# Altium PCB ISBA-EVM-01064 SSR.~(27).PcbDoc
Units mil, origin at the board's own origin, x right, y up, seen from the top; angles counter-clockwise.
Board outline 2700 x 2000 mil, 2 copper layers (Top Layer, Bottom Layer), stack 62 mil thick; 83 components, 26 nets, 153 pads, 165 vias.
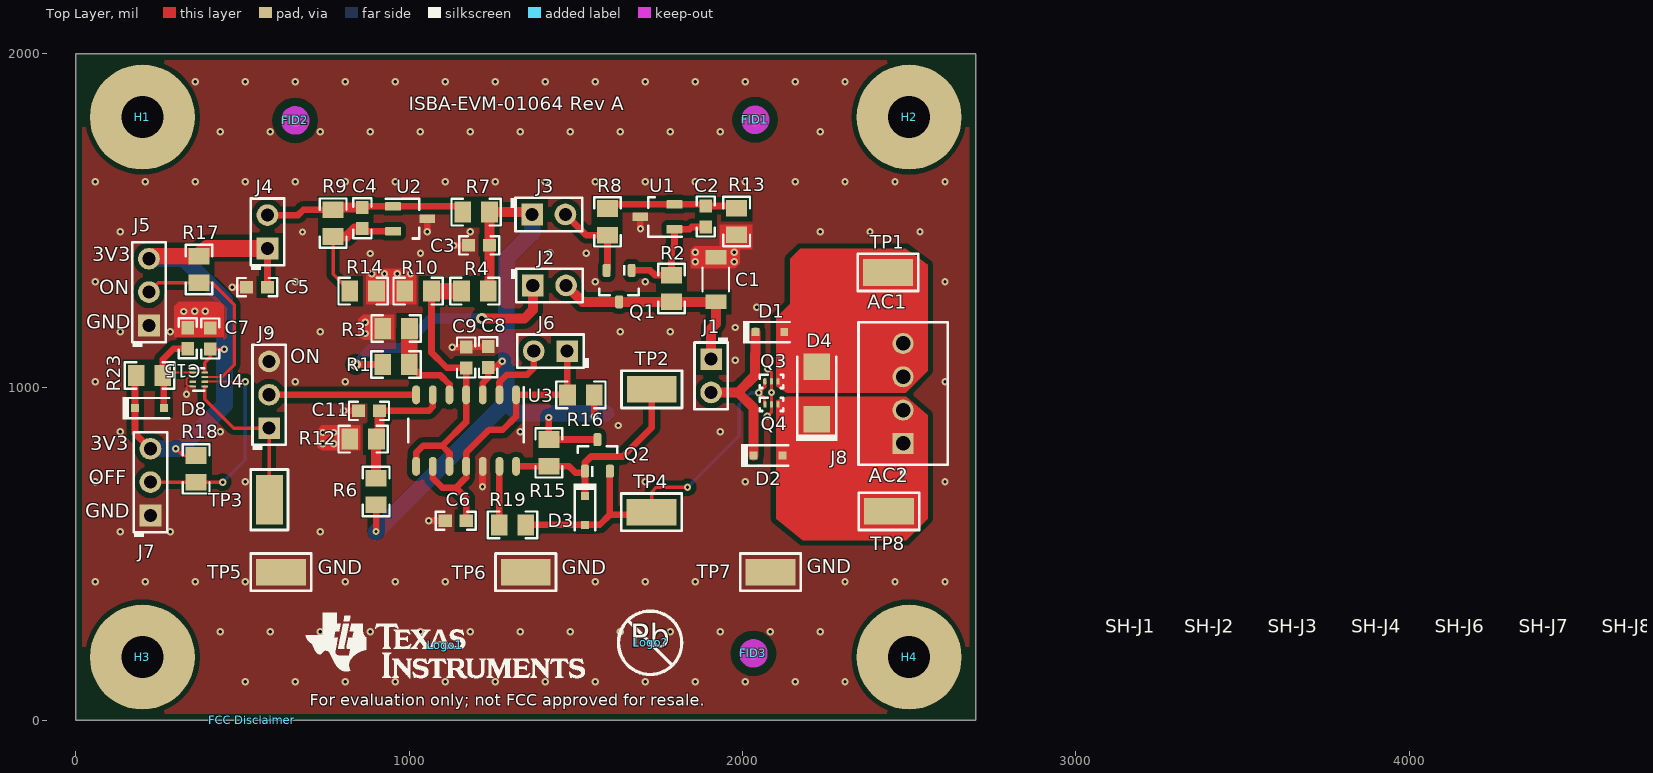
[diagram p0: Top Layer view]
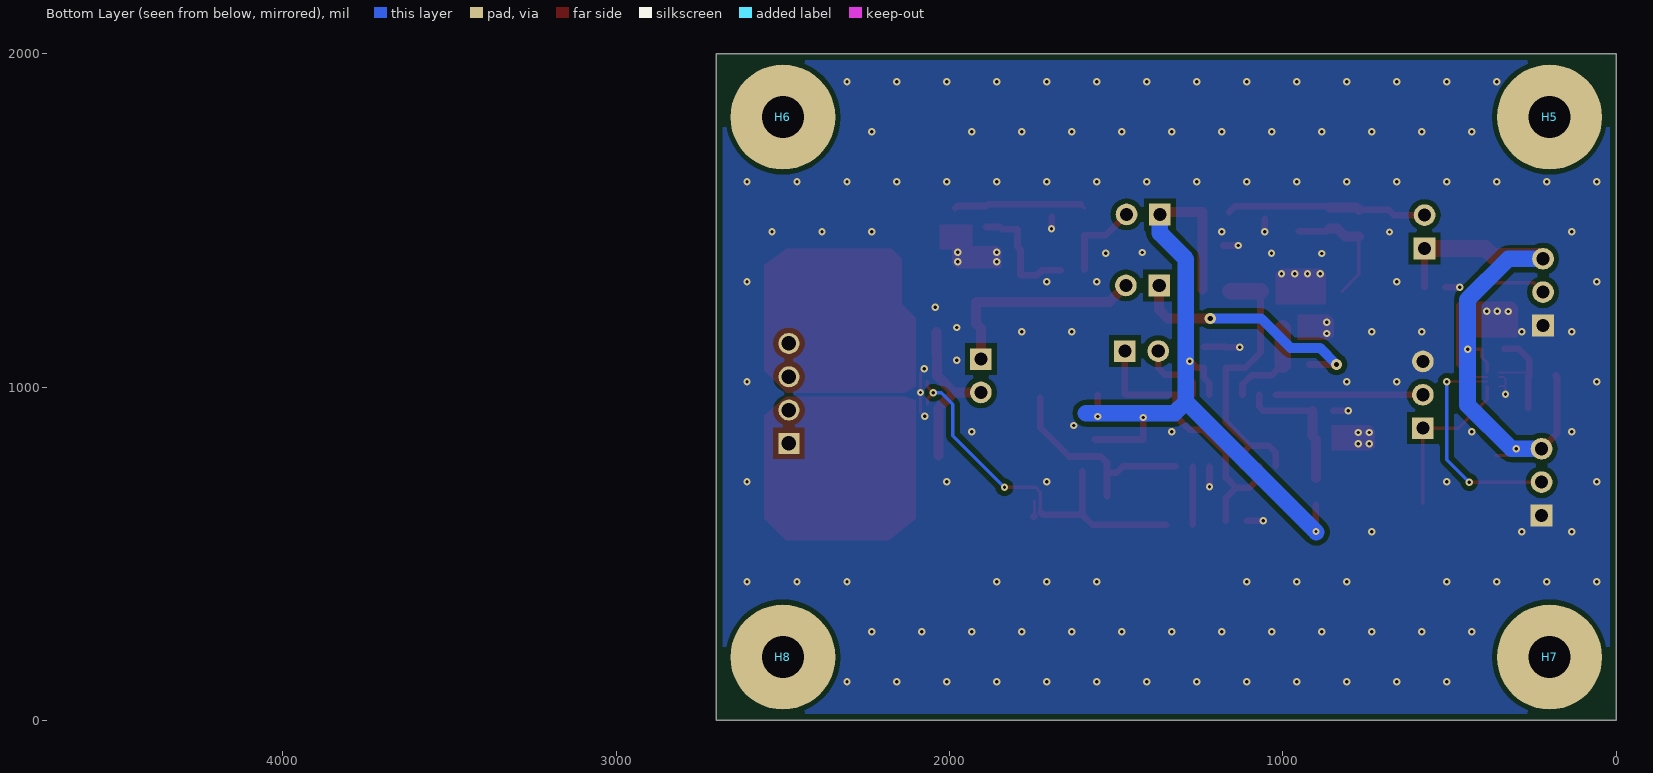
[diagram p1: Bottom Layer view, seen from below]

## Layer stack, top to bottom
Top Solder: solder mask 0.4, Solder Resist, Dk 3.5
Top Layer: signal copper 1.4
Dielectric1: core 59.2, FR-4, Dk 4.8
Bottom Layer: signal copper 1.4
Bottom Solder: solder mask 0.4, Solder Resist, Dk 3.5

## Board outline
0,0 2700,0 2700,2000 0,2000

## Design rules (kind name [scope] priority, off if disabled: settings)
AcuteAngle [All] p1: minimum=4.50000000000000E+0001 checktracksonly=FALSE
AssemblyTestPointUsage [All] p1: valid=2
Clearance Clearance_BoardEdge_MountingHoles [OnCopper and InComponentClass('Mounting Holes') vs IsKeepOut] p1: gap=25
Clearance Clearance_BoardEdge_Poly [OnCopper and InPoly vs IsKeepOut] p2: gap=25
Clearance Clearance_BoardEdge [OnCopper and Not InComponentClass('Logo') and not InComponentClass('FiducialMark') and not InRegion(1000,500,4000,800) and Not IsKeepout vs IsKeepOut] p3: gap=25
Clearance Clearance_Poly [InPolygon] p4: gap=15
Clearance [All] p5: gap=7
ComponentClearance ComponentClearance_Shunt [InComponentClass('Header') vs InComponentClass('Shunt')] p1: gap=0 collisioncheckmode=3 verticalgap=0 showdistances=FALSE
ComponentClearance ComponentClearance_Logo [InComponentClass('Logo')] p2: gap=50 collisioncheckmode=3 verticalgap=10 showdistances=FALSE
ComponentClearance ComponentClearance_ScrewToNut [(HasFootprint('NY PMS 440 0025 PH')) vs (HasFootprint('Keystone_1902C'))] p3: gap=5 collisioncheckmode=3 verticalgap=10 showdistances=FALSE
ComponentClearance ComponentClearance_MountingHoles [InComponentClass('Mounting Holes')] p4: gap=250 collisioncheckmode=3 verticalgap=100000 showdistances=FALSE
ComponentClearance ComponentClearance_SmallPassives [HasFootprint('0201*') or HasFootprint('0402*') or HasFootprint('0508') or HasFootprint('0603*') or HasFootprint('0612') or HasFootprint('0805*') or HasFootprint('0815*') or HasFootprint('0830*') or HasFootprint('1206*') or HasFootprint('1210*') or HasFootprint('1808*') or HasFootprint('1812*') or HasFootprint('1825*') or HasFootprint('2010*') or HasFootprint('2220*') or HasFootprint('2225*') or HasFootprint('2512*') or HasFootprint('2728*') or HasFootprint('3518*') vs HasFootprint('0201*') or HasFootprint('0402*') or HasFootprint('0508') or HasFootprint('0603*') or HasFootprint('0612') or HasFootprint('0805*') or HasFootprint('0815*') or HasFootprint('0830*') or HasFootprint('1206*') or HasFootprint('1210*') or HasFootprint('1808*') or HasFootprint('1812*') or HasFootprint('1825*') or HasFootprint('2010*') or HasFootprint('2220*') or HasFootprint('2225*') or HasFootprint('2512*') or HasFootprint('2728*') or HasFootprint('3518*')] p5: gap=15 collisioncheckmode=3 verticalgap=10 showdistances=FALSE
ComponentClearance ComponentClearance_THtoSMT [IsThruComponent vs IsSMTComponent] p6: gap=50 collisioncheckmode=3 verticalgap=30 showdistances=FALSE
ComponentClearance ComponentClearance_THtoTH [IsThruComponent vs IsThruComponent] p7: gap=50 collisioncheckmode=3 verticalgap=30 showdistances=FALSE
ComponentClearance [All] p8: gap=40 collisioncheckmode=3 verticalgap=10 showdistances=FALSE
DiffPairsRouting [All] p1: maxlimit=100 minlimit=10 mostfreqgap=10 toplayer_minwidth=15 toplayer_maxwidth=15 toplayer_prefwidth=15 bottomlayer_minwidth=15 bottomlayer_maxwidth=15 bottomlayer_prefwidth=15 maxuncoupledlength=1000
FabricationTestPointUsage TestPointUsage [All] p1: valid=2 allowmultiple=FALSE
FabricationTestpoint Testpoint [All] p1: side=3 testpointundercomponent=TRUE minsize=40 maxsize=100 preferedsize=60 minholesize=0 maxholesize=40 preferedholesize=32 testpointgrid=1 allowsidetop=TRUE allowsidebottom=TRUE usegrid=TRUE gridtolerance=0.01
FanoutControl Fanout_LCC [IsLCC] p1: bgadir=Out bgaviamode=Centered fanoutstyle=Auto fanoutdirection=Alternating viagrid=1 // Fanout_LCC (Default Rule)
FanoutControl Fanout_BGA [IsBGA] p2: bgadir=Out bgaviamode=Centered fanoutstyle=Auto fanoutdirection=Alternating viagrid=1 // Fanout_BGA (Default Rule)
FanoutControl Fanout_Default [All] p4: bgadir=Out bgaviamode=Centered fanoutstyle=Auto fanoutdirection=Alternating viagrid=1 // Fanout_Default (Default Rule)
FanoutControl Fanout_Small [(CompPinCount < 5)] p5: bgadir=Out bgaviamode=Centered fanoutstyle=Auto fanoutdirection=OutThenIn viagrid=1 // Fanout_Small (Default Rule)
HoleSize [All] p1: absolutevalues=TRUE maxlimit=251 minlimit=8 maxpercent=80.000 minpercent=20.000
MinimumAnnularRing MinimumAnnularRing_ThermalPadVias [IsVia and InAnyComponent] p1: minimumring=5.91
MinimumAnnularRing [All] p2: minimumring=5
MinimumSolderMaskSliver MinimumSolderMaskSliver_Logo [InComponentClass('Logo') vs InComponentClass('Logo')] p1: minsoldermaskwidth=0.7
MinimumSolderMaskSliver [All] p2: minsoldermaskwidth=3.94
PlaneClearance [All] p1: clearance=15
PlaneConnect [All] p1: planeconnectstyle=Direct reliefexpansion=10 reliefentries=4 reliefconductorwidth=10 reliefairgap=10
PolygonConnect [All] p1: connectstyle=Direct reliefconductorwidth=10 reliefentries=4 polygonreliefangle="90 Angle" airgapwidth=10
RoutingVias ThermalPadVias [IsVia and InAnyComponent] p1: holewidth=7.87 width=19.68 viastyle="Through Hole" minholewidth=7.87 minwidth=19.68 maxholewidth=12.99 maxwidth=23.62
RoutingVias [All] p2: holewidth=16 width=34 viastyle="Through Hole" minholewidth=7.87 minwidth=19 maxholewidth=40 maxwidth=65
SMDToCorner [All] p1: distance=30000
SilkToBoardRegionClearance [Not ((IsComment or IsDesignator) And (Hide <> 'False')) and not InRegion(1000,500,4000,800)] p1:
SilkToSilkClearance [All] p1: silktosilkclearance=0
SilkToSolderMaskClearance SilkscreenOverComponentPads [IsPad] p1: minsilkscreentomaskgap=0 clearancetoexposedcopper=TRUE
SolderMaskExpansion [All] p1: expansion=1.97
Width [All] p1: maxlimit=100 minlimit=6 preferedwidth=10 checkconnectedcopper=TRUE
14 further rules are at their usual default settings.

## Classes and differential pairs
component class Shunt: SH-J1 SH-J2 SH-J3 SH-J4 SH-J6 SH-J7 SH-J8
component class "ISBA-EVM-01064 SSR_Relay": C1 C2 C3 C4 C5 C6 C7 C8 C9 C11 C15 D1 D2 D3 D4 D8 J1 J2 J3 J4 J5 J6 J7 J8 J9 Q1 Q2 Q3 Q4 R1 R2 R3 R4 R6 R7 R8 R9 R10 R12 R13 R14 R15 R16 R17 R18 R19 R23 TP1 TP2 TP3 TP4 TP5 TP6 TP7 TP8 U1 U2 U3 U4
component class Header: J1 J2 J3 J4 J5 J6 J7 J9
component class "Mounting Holes": H1 H2 H3 H4
component class Logo: Logo1
component class "ISBA-EVM-01064 SSR_TID_Hardware": "FCC Disclaimer" FID1 FID2 FID3 H1 H2 H3 H4 H5 H6 H7 H8 Logo1 Logo? SH-J1 SH-J2 SH-J3 SH-J4 SH-J6 SH-J7 SH-J8 ZZ1 ZZ2 ZZ3
component class FiducialMark: FID1 FID2 FID3
component class AssemblyNote: ZZ1 ZZ2 ZZ3

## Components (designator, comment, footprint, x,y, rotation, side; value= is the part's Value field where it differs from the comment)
C1 "CL31B105KCHNNNE" 1206_180 1920,1322.68 r90 top
C2 "GRM1885C1H201JA01D" 0603 1890,1512 r90 top
C3 "GRM188R61E105KA12D" 0603 1210,1425 r180 top
C4 "GRM1885C1H201JA01D" 0603 860,1507 r270 top
C5 "GRM188R61E105KA12D" 0603 544,1300 r180 top
C6 "GRM188R61E105KA12D" 0603 1140,599 r180 top
C7 "GRM188R71C104KA01D" 0603 403.5,1146 r270 top
C8 "GRM188R71C104KA01D" 0603 1237,1090 r270 top
C9 "GRM188R71C104KA01D" 0603 1171,1089 r270 top
C11 "GRM188R71C104KA01D" 0603 879.68,928.69 r0 top
C15 "C0603C101J5GACTU" 0603 336,1146.5 r90 top
D1 "1N4448WX-TP" sod-323 2082,1165 r0 top
D2 "1N4448WX-TP" sod-323 2077,795 r0 top
D3 "1N4448WX-TP" sod-323 1527.6,630 r270 top
D4 "SMAJ40CA" SMA 2223,982 r90 top
D8 "1N4448WX-TP" sod-323 221,937 r0 top
"FCC Disclaimer" "FCC disclaimer" FCC_disclaimer 530,0 r90 top
FID1 "Fiducial" Fiducial10-20 2038,1802 r0 top
FID2 "Fiducial" Fiducial10-20 658,1800 r0 top
FID3 "Fiducial" Fiducial10-20 2033,201 r0 top
H1 "NY PMS 440 0025 PH" "NY PMS 440 0025 PH" 200,1810 r0 top locked
H2 "NY PMS 440 0025 PH" "NY PMS 440 0025 PH" 2500,1810 r0 top locked
H3 "NY PMS 440 0025 PH" "NY PMS 440 0025 PH" 200,190 r0 top locked
H4 "NY PMS 440 0025 PH" "NY PMS 440 0025 PH" 2500,190 r0 top locked
H5 "1902C" Keystone_1902C 200,1810 r180 bottom locked
H6 "1902C" Keystone_1902C 2500,1810 r180 bottom locked
H7 "1902C" Keystone_1902C 200,190 r180 bottom locked
H8 "1902C" Keystone_1902C 2500,190 r180 bottom locked
J1 "5-146278-2" TE_5-146278-2 1906,1034 r270 top
J2 "5-146278-2" TE_5-146278-2 1421,1305 r0 top
J3 "5-146278-2" TE_5-146278-2 1419,1518 r0 top
J4 "5-146278-2" TE_5-146278-2 575,1466 r90 top
J5 "5-146278-3" TE_5-146278-3 219.61,1285 r90 top
J6 "5-146278-2" TE_5-146278-2 1424,1108 r180 top
J7 "5-146278-3" TE_5-146278-3 224,715 r90 top
J8 "282834-4" TEC_282834-4 2482,981 r90 top
J9 "5-146278-3" TE_5-146278-3 580,977 r90 top
Logo1 "Texas Instruments" TI_Stacked_Overlay_Small 1109,225 r0 top
Logo? "Pb-Free Symbol" Pb-Free_Overlay_Medium 1723,233 r0 top
Q1 "MMBTA05LT1G" SOT-23 1630,1303 r270 top
Q2 "MMBT3904LT1G" SOT-23 1565,795 r90 top
Q3 "CSD18541F5" YJK0003A 2087,1017 r0 top
Q4 "CSD18541F5" YJK0003A 2087.3,948 r0 top
R1 "CRCW080510M0FKEA" 0805_HV 960.71,1068 r0 top
R2 "CRCW0805205KFKEA" 0805_HV 1787,1296 r270 top
R3 "CRCW08053M09FKEA" 0805_HV 961,1176 r0 top
R4 "CRCW080510M0FKEA" 0805_HV 1197,1288 r0 top
R6 "RC0805JR-0733ML" 0805_HV 901,687 r270 top
R7 "CRCW0805100KFKEA" 0805_HV 1201,1525 r0 top
R8 "CRCW08053M74FKEA" 0805_HV 1595,1496 r270 top
R9 "CRCW0805806KFKEA" 0805_HV 772,1492 r90 top
R10 "CRCW08057M50FKEA" 0805_HV 1027,1288 r0 top
R12 "CRCW08056M49FKEA" 0805_HV 862,844 r0 top
R13 "CRCW08051M30FKEA" 0805_HV 1982.94,1497 r90 top
R14 "CRCW08052M80FKEA" 0805_HV 862,1288 r180 top
R15 "CRCW080590K9FKEA" 0805_HV 1419,803 r90 top
R16 "CRCW0805665KFKEA" 0805_HV 1515,977 r0 top
R17 "CRCW0805124KFKEA" 0805_HV 369.8,1352.89 r90 top
R18 "CRCW0805124KFKEA" 0805_HV 361,755 r90 top
R19 "CRCW08050000Z0EA" 0805_HV 1310,587 r0 top
R23 "CRCW0805100KFKEA" 0805_HV 221,1035 r0 top
SH-J1 "SPC02SYAN" SPC02SYAN 3131,135 r90 top
SH-J2 "SPC02SYAN" SPC02SYAN 3368,135 r90 top
SH-J3 "SPC02SYAN" SPC02SYAN 3619,135 r90 top
SH-J4 "SPC02SYAN" SPC02SYAN 3869,135 r90 top
SH-J6 "SPC02SYAN" SPC02SYAN 4120,135 r90 top
SH-J7 "SPC02SYAN" SPC02SYAN 4371,135 r90 top
SH-J8 "SPC02SYAN" SPC02SYAN 4621,135 r90 top
TP1 "TESTPOINT" Keystone_5019#1 2436.23,1344 r180 top
TP2 "TESTPOINT" Keystone_5019#1 1728,993.18 r0 top
TP3 "TESTPOINT" Keystone_5019#1 581,662 r270 top
TP4 "TESTPOINT" Keystone_5019#1 1727.72,625 r180 top
TP5 "TESTPOINT" Keystone_5019#2 616,445 r180 top
TP6 "TESTPOINT" Keystone_5019#1 1350,445 r0 top
TP7 "TESTPOINT" Keystone_5019#1 2084,445 r0 top
TP8 "TESTPOINT" Keystone_5019#1 2440,627 r180 top
U1 "ATL431AIDBZR" DBZ0003A_M 1745,1511 r180 top
U2 "ATL431AIDBZR" DBZ0003A_M 1003,1505 r0 top
U3 "LP339D" D0014A_N 1171,869.68 r270 top
U4 "SN74AUP1G74DQER" DQE0008A 369,1023 r0 top
ZZ1 "These assemblies are ESD sensitive, ESD precautions shall be observed." AssemblyNote 185,3829.11 r0 top
ZZ2 "These assemblies must be clean and free from flux and all contaminants. Use of no clean flux is not acceptable." AssemblyNote 185,3740.56 r0 top
ZZ3 "These assemblies must comply with workmanship standards IPC-A-610 Class 2, unless otherwise specified." AssemblyNote 185,3652 r0 top

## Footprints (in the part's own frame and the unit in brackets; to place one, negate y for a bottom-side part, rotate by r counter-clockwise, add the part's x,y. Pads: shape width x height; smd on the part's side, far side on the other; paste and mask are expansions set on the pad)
0603 [mm] "0603 from SM-752 data"
  rect 1x0.95 smd: 1(-0.8,0) 2(0.8,0)
  silkscreen extent -1.52,-0.69 1.52,0.69, body extent -0.87,-0.47 0.87,0.47, height 1
0805_HV [mil] "0805 with 30mil clearance between pads"
  rect 50x63 smd: 1(-40,0) 2(40,0)
  silkscreen extent -74,-40 74,40, body extent -43,-29 43,29, height 57
1206_180 [mm] "1206_180"
  rect 1.1x1.6 smd: 1(-1.7,0) 2(1.7,0)
  silkscreen extent -0.9,-1 0.9,1, body extent -1.75,-0.95 1.75,0.95, height 1.8
AssemblyNote [mil] "Assembly Note"
D0014A_N [mm] "SOIC, 14-Leads, Body 8.7x3.9mm, Pitch 1.27mm, IPC Medium Density"
  oval 1.45x0.6 smd: 1(-2.725,3.81) 2(-2.725,2.54) 3(-2.725,1.27) 4(-2.725,0) 5(-2.725,-1.27) 6(-2.725,-2.54) 7(-2.725,-3.81) 8(2.725,-3.81) 9(2.725,-2.54) 10(2.725,-1.27) 11(2.725,0) 12(2.725,1.27) 13(2.725,2.54) 14(2.725,3.81)
  silkscreen extent -3.3,-4.4 0.9,4.4, body extent -3.02,-4.32 3.02,4.32, height 1.6
DBZ0003A_M [mm] "SOT23, 3-Leads, Body 2.9x1.3mm, Pitch 0.95mm, Lead Span 2.4mm, IPC Low Density"
  rrect15% 1.2x0.65 smd: 1(-1.3,0.95) 2(-1.3,-0.95) 3(1.3,0)
  silkscreen extent -1.85,-1.5 0.7,1.53, body extent -1.26,-1.46 1.26,1.46, height 0.98
DQE0008A [mm] "SON, 8-Leads, Body 1.4x1mm, Pitch 0.35mm, TI Recommended"
  rect 0.6x0.16 smd mask+0: 1(-0.4,0.525)
  rect 0.5x0.16 smd mask+0: 2(-0.45,0.175) 3(-0.45,-0.175) 4(-0.45,-0.525) 5(0.45,-0.525) 6(0.45,-0.175) 7(0.45,0.175) 8(0.45,0.525)
  silkscreen extent -0.7,-0.85 0.4,0.85, body extent -0.53,-0.72 0.53,0.73, height 0.41
FCC_disclaimer [mil]
Fiducial10-20 [mm]
  round 1 smd mask+0.5: 1(0,0)
  Top Layer keep-out circle w1.178: c0,0 r0.5
Keystone_1902C [mil] "Hex Standoff, 4-40 threaded, nylon"
  body extent -145,-126 146,126, height 501
Keystone_5019#1 [mm] "Test Point, Miniature, SMT"
  rect 3.8x2.03 smd: 1(0,0)
  silkscreen extent -2.31,-1.42 2.31,1.42, body extent -1.9,-1.02 1.9,1.02, height 2.29
Keystone_5019#2 [mm] "Test Point, Miniature, SMT"
  rect 3.8x2.03 smd: 1(0.006,0)
  silkscreen extent -2.31,-1.42 2.31,1.42, body extent -1.9,-1.02 1.9,1.02, height 2.29
"NY PMS 440 0025 PH" [mm] "4-40 nylon screw and mounting hole"
  round 8 hole 3.2: 1(0,0)
  body extent -3.3,-3.3 3.3,3.3, height 2.69
Pb-Free_Overlay_Medium [mil]
  silkscreen extent -95,-95 95,95
SMA [mm] "Molded Diode, 2-Leads, Body 4.3x2.6mm, IPC Medium Density, based on OnSemi component dimensions and land pattern"
  rect 2x2 smd: 1(-2,0) 2(2,0)
  silkscreen extent -3.66,-1.57 2.79,1.57, body extent -2.6,-1.3 2.6,1.3, height 2.42
sod-323 [mm] "NXP recommended land pattern"
  rect 0.6x0.6 smd paste-0.05: 1(-1.1,0) 2(1.1,0)
  silkscreen extent -2.06,-0.86 1.53,0.86, body extent -1.3,-0.67 1.3,0.68, height 1.1
SOT-23 [mm] "SOT23, 3-Leads, Body 2.9x1.3mm, Pitch 0.95mm, Lead Span 2.5mm, IPC Medium Density"
  rrect50% 1x0.6 smd: 1(-1.2,0.95) 2(-1.2,-0.95) 3(1.2,0)
  silkscreen extent -1.63,-1.5 0.7,1.5, body extent -1.16,-1.45 1.21,1.45, height 1
SPC02SYAN [mil] "SULLINS"
  round 1 on Mech3: 0(0,0)
  body extent -98,-47 99,47, height 366
TE_5-146278-2 [mm] "TE CONNECTIVITY"
  rect 1.65x1.65 hole 1: 1(-1.27,0)
  round 1.65 hole 1: 2(1.27,0)
  silkscreen extent -2.92,-1.27 2.54,1.27, body extent -2.41,-1.17 2.41,1.17, height 8.13
TE_5-146278-3 [mm] "TE CONNECTIVITY"
  rect 1.65x1.65 hole 1: 1(-2.54,0)
  round 1.65 hole 1: 2(0,0) 3(2.54,0)
  silkscreen extent -4.19,-1.27 3.81,1.27, body extent -3.68,-1.17 3.68,1.17, height 8.13
TEC_282834-4 [mm] "TEC"
  rect 1.6x1.6 hole 1.1: 1(-3.81,0)
  round 1.6 hole 1.1: 2(-1.27,0) 3(1.27,0) 4(3.81,0)
  silkscreen extent -6.2,-3.4 5.44,3.4, body extent -5.31,-3.25 5.31,3.25, height 10.02
TI_Stacked_Overlay_Small [mil]
  silkscreen extent -418,-98 418,98
YJK0003A [mm] "SMD, 3-Leads, Body 1.49x0.73mm"
  rrect80% 0.25x0.49 smd paste-0.05 mask-0.05: 1(-0.5,0) 2(0,0) 3(0.5,0)
  silkscreen extent -0.9,-0.5 0.9,0.5, body extent -0.75,-0.37 0.74,0.36, height 0.35

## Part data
C1: "CAP, CERM, 1 µF, 100 V, +/- 10%, X7R, 1206"
C2 C4: "CAP, CERM, 200 pF, 50 V, +/- 5%, C0G/NP0, 0603"
C3 C5 C6: "CAP, CERM, 1 µF, 25 V, +/- 10%, X5R, 0603"
C7 C8 C9 C11: "CAP, CERM, 0.1 µF, 16 V, +/- 10%, X7R, 0603"
C15: "CAP, CERM, 100 pF, 50 V, +/- 5%, C0G/NP0, 0603"
D1 D2 D3 D8: "Diode, Switching, 75 V, 0.25 A, SOD-323"
D4: "Diode, TVS, Bi, 40 V, 400 W, SMA"
"FCC Disclaimer": library part FCC_disclaimer, "FCC_disclaimer"
FID1 FID2 FID3: "Fiducial mark.  There is nothing to buy or mount."
H1 H2 H3 H4: "Machine Screw, Round, #4-40 x 1/4, Nylon, Philips panhead"
H5 H6 H7 H8: "Standoff, Hex, 0.5\"L #4-40 Nylon"
J1 J2 J3 J4 J6: "Header, 100mil, 2x1, Tin, TH"
J5 J7 J9: "Header, 100mil, 3x1, Tin, TH"
J8: "Terminal Block, 100mil, 4X1 TH"
Logo1: library part TI_Logo, "Texas Instrument Corporate Signature"
Logo?: library part Pb-Free
Q1: library part "MMBTA05LT1G, ON Semiconductor", "Transistor, NPN, 60 V, 0.5 A, AEC-Q101, SOT-23"
Q2: library part "MMBT3904LT1G, ON Semiconductor", "Transistor, NPN, 40 V, 0.2 A, SOT-23"
Q3 Q4: "MOSFET, N-CH, 60 V,  A, PICOSTAR-3"
R1 R4: "RES, 10.0 M, 1%, 0.125 W, 0805"
R2: "RES, 205 k, 1%, 0.125 W, 0805"
R3: "RES, 3.09 M, 1%, 0.125 W, 0805"
R6: "RES, 33 M, 5%, 0.125 W, 0805"
R7 R23: "RES, 100 k, 1%, 0.125 W, 0805"
R8: "RES, 3.74 M, 1%, 0.125 W, 0805"
R9: "RES, 806 k, 1%, 0.125 W, 0805"
R10: "RES, 7.50 M, 1%, 0.125 W, 0805"
R12: "RES, 6.49 M, 1%, 0.125 W, 0805"
R13: "RES, 1.30 M, 1%, 0.125 W, 0805"
R14: "RES, 2.80 M, 1%, 0.125 W, 0805"
R15: "RES, 90.9 k, 1%, 0.125 W, 0805"
R16: "RES, 665 k, 1%, 0.125 W, 0805"
R17 R18: "RES, 124 k, 1%, 0.125 W, 0805"
R19: "RES, 0, 5%, 0.125 W, 0805"
SH-J1 SH-J2 SH-J3 SH-J4 SH-J6 SH-J7 SH-J8: "Shunt, 100mil, Flash Gold, Black"
TP1 TP2 TP3 TP4 TP5 TP6 TP7 TP8: library part 5019, "Test Point, Miniature, SMT"
U1 U2: "2.5V Low Iq Adjustable Precision Shunt Regulator, DBZ0003A"
U3: "Quad, Low-Power, General Purpose Differential Comparator, D0014A"
U4: "LOW-POWER SINGLE POSITIVE-EDGE-TRIGGERED D-TYPE FLIP-FLOP WITH CLEAR AND PRESET, DQE0008A"
ZZ1 ZZ2 ZZ3: library part AssemblyNote

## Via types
v1: diameter 22, hole 10, Top Layer to Bottom Layer, tented both sides, 163 vias
v2: diameter 34, hole 16, Top Layer to Bottom Layer, tented both sides, 2 vias

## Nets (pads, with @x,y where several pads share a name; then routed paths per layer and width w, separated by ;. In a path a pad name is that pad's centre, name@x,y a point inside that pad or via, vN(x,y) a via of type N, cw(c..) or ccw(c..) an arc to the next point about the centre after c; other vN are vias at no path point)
3.3V: C5.1 C7.2 D8.1 J4.1 J5.3 J7.3 R17.2 R18.2 R23.1 U4.8 | length 1780.5
  Top Layer w10: v1(300,815.49) 320.49,795 R18.2 ; U4.8@386.72,1046.04 386.72,1072.52 403.5,1089.3 C7.2 404.51,1113.49 v1(445,1113.49)
  Top Layer w20: R23.1 177.69,1031.69 D8.1 177.69,861.31 J7.3 ; C5.1@575,1300.5 J4.1
  Top Layer w50: J5.3 227.5,1392.89 R17.2 392.91,1416 J4.1
  Bottom Layer w50: J5.3 323.19,1385 446,1262.19 446,946.5 314.5,815 J7.3
10V: C3.1 C8.2 J3.1 Q2.3 R4.2 R6.2 R7.2 R15.2 R16.2 U3.3 | length 2326.7
  Top Layer w10: U3.3@1220,977.97 U3.3 ; R4.2 R4.2@1241.5,1292.5 ; C3.1@1241,1425.5 C3.1 ; J3.1@1362,1525 J3.1
  Top Layer w20: v1@901,567.14 R6.2 ; U3.3 1221,1012 1237,1028 C8.2 1259.5,1058.5 v1(1279,1078) ; v1(1419,909) R15.2 Q2.3@1564.24,843 ; v1(1555,912) R16.2
  Top Layer w30: C3.1@1241,1425.5 R7.2 J3.1@1362,1525 ; R4.2@1241.5,1292.5 C3.1
  Bottom Layer w50: v1@900,565 1291,956 ; J3.1 1369,1462 1291,1384 1291,956 ; 1590.6,921.75 1555.01,921.78 1419.01,921.91 1325,922 1291,956
  other v1: 900.86,567
EN: J9.2 U3.7 | length 441
  Top Layer w20: J9.2 U3.7
GND: C1.2 C3.2 C5.2 C6.2 C7.1 C8.1 C9.1 C11.1 C15.2 J5.1 J7.1 J9.3 Q3.2 Q4.2 R3.1 R10.1 R12.1 R13.1 R14.1 TP5.1 TP6.1 TP7.1 U1.3 U2.3 U3.12 U4.2 U4.4 | length 665.7
  Top Layer w6: v1(332,979) 332,997.66 337.3,1002.96 ; U4.4 350.65,1002.96 337.3,1002.96 ; U4.2 337.93,1029.89 331.44,1023.4 331.44,1008.82 337.3,1002.96
  Top Layer w10: R10.1@987,1285 R10.1 ; v1(1220,701) v1@1221,702 ; v1(2074.69,912.93) 2087.3,925.54 Q4.2 v1(2087.3,984) 2087.3,1016.71 Q3.2 2087,1044.11 v1(2076.44,1054.68)
  Top Layer w20: v1(469,1300) C5.2 ; v1@804.31,928.69 C11.1 ; v1(1054,1466.41) 1054,1504.82 U2.3 ; v1@1059.9,599 C6.2 ; v1(1129,1120) 1170.5,1120 C9.1 1172,1121.5 C8.1 ; v1(1134,1425) C3.2 ; v1(1220,701) U3.12@1220,761.4 ; v1@1693.82,1475.18 U1.3
  other v1: 508,116 658,116 808,116 958,116 1108,116 1258,116 1408,116 1558,116 1708,116 1858,116 2008,116 2158,116 2308,116 433,266 583,266 733,266 883,266 1033,266 1183,266 1333,266 1483,266 1633,266 1783,266 1933,266 2083,266 2233,266 58,416 208,416 358,416 508,416 808,416 958,416 1108,416 1558,416 1708,416 1858,416 2308,416 2458,416 2608,416 133,566 283,566 733,566 1059.4,599.5 58,716 508,716 1708,716 2008,716 2608,716 741,830 774,830 741,864 774,864 133,866 433,866 1333,866 1933,866 1627.89,885 804,929 58,1016 658,1016 808,1016 2608,1016 1978.44,1080.68 868,1161 133,1166 283,1166 583,1166 733,1166 1633,1166 1783,1166 1978.32,1179 868,1195 324,1227 357,1227.4 388,1227.4 2043.44,1239.55 58,1316 658,1316 1558,1316 1708,1316 2608,1316 888,1340 926,1340 964,1340 1004,1340 1858.15,1376 1975.58,1376 883.44,1400.68 1034.06,1402 1531.44,1401.68 1422.03,1403.68 1858.15,1405 1975.58,1405 680.38,1465.21 133,1466 1183,1466 2233,1466 2383,1466 2533,1466 1694,1475 58,1616 208,1616 358,1616 508,1616 658,1616 808,1616 958,1616 1108,1616 1258,1616 1408,1616 1558,1616 1708,1616 1858,1616 2008,1616 2158,1616 2308,1616 2458,1616 2608,1616 433,1766 583,1766 733,1766 883,1766 1033,1766 1183,1766 1333,1766 1483,1766 1633,1766 1783,1766 1933,1766 2233,1766 358,1916 508,1916 658,1916 808,1916 958,1916 1108,1916 1258,1916 1408,1916 1558,1916 1708,1916 1858,1916 2008,1916 2158,1916 2308,1916
HV1: D1.2 D4.2 J8.3 J8.4 Q3.3 TP1.1
HV2: D2.2 D4.1 J8.1 J8.2 Q4.3 TP8.1 | length 1.8
  Top Layer w20: D4.1@2221.74,902 D4.1
NetC1_1: C1.1 J1.1 J2.2 Q1.3 R2.2 | length 647.1
  Top Layer w30: J2.2 1520.24,1255.76 Q1.3 ; Q1.3@1630,1255.36 1800,1256 1800.24,1255.76 C1.1 1920,1189.86 1906,1175.86 J1.1
NetC2_1: C2.1 Q1.1 R2.1 U1.1 | length 363.6
  Top Layer w20: Q1.1 1723,1350.24 1737.24,1336 R2.1 1787,1412.82 1796.18,1422 U1.1 1841.12,1473.6 1848.02,1480.5 C2.1
NetC2_2: C2.2 R8.1 R13.2 U1.2 | length 397.8
  Top Layer w10: R8.1 R8.1@1607.4,1548.4 ; C2.2@1885.09,1548.4 C2.2
  Top Layer w20: R8.1@1607.4,1548.4 U1.2 C2.2@1885.09,1548.4 ; C2.2 1976.44,1543.5 R13.2
NetC4_1: C4.1 J4.2 R7.1 R9.2 U2.1 | length 609.5
  Top Layer w10: U2.1@947.91,1538.5 U2.1
  Top Layer w20: J4.2 667,1516 683,1532 R9.2 ; C4.1 863.5,1542 U2.1 1143.6,1542.4 R7.1
  Top Layer w30: R9.2 778.5,1538.5 C4.1
NetC4_2: C4.2 R9.1 R14.2 U2.2 | length 377.5
  Top Layer w10: R9.1 772,1338 R14.2
  Top Layer w20: C4.2 867.91,1467.6 U2.2
  Top Layer w30: R9.1 813,1452 836.5,1475.5 C4.2
NetC6_1: C6.1 J6.1 R16.1 U3.1 U3.9 U3.11 | length 891.4
  Top Layer w10: R16.1@1471.71,977 R16.1@1474,979.29 ; J6.1 J6.1@1475,1107
  Top Layer w20: U3.9 1071,726.91 1099.91,698 1140.61,698 ; C6.1@1171,599.5 C6.1 1171.5,667.12 1140.61,698 ; R16.1@1471.71,977 U3.1 1321,912 1281,872 1240,872 1171,803 U3.11 1171,728.39 1140.61,698 ; R16.1@1474,979.29 J6.1
NetD1_1: D1.1 D2.1 J1.2 | length 493.2
  Top Layer w30: J1.2@1900,983 J1.2@1901,984 ; J1.2 1987,984 ; D2.1 2033.69,937.31 1987,984 ; D1.1 2038.69,1099.75 2038.39,1099.45 2038.39,1035.39 1987,984
NetD3_1: D3.1 Q2.1 R15.1 TP2.1 U3.14 | length 643.1
  Top Layer w10: R15.1@1418.4,762.4 R15.1
  Top Layer w20: U3.14 R15.1@1418.4,762.4 ; R15.1 1479,763 1499,743 Q2.1@1527.35,743 ; D3.1 Q2.1@1527.6,742.76 ; Q2.1@1528,743.65 Q2.1@1527.6,743.24 ; 1728,879 1641,792 1546.04,792 1527.6,773.55 Q2.1 Q2.1@1527.6,743.24 ; 1728,885.04 TP2.1@1728,967.69 ; Q2.1@1527.35,743 Q2.1@1527.6,742.76 ; Q2.1@1527.35,743 Q2.1@1527.6,743.24 ; Q2.1@1527.6,742.76 Q2.1@1527.6,743.24
NetD3_2: D3.2 Q2.2 Q3.1 Q4.1 R19.2 TP4.1 | length 1218.5
  Top Layer w10: TP4.1 1727.72,684.72 1742.21,699.21 v1(1835.44,699.21) ; TP4.1@1745,611.82 TP4.1@1745,658.58 ; Q4.1@2066.32,948 2066.32,965.68 v1(2049,983) 2050,983 2067.32,1000.32 Q3.1
  Top Layer w20: R19.2 D3.2 1527.91,587 1572,587 1602.31,617.31 ; Q2.2 1602.4,653.09 1602.31,653 1602.31,617.31 ; TP4.1 1720.03,617.31 1602.31,617.31 ; TP4.1@1745,611.82 TP4.1@1748.6,611.82
  Bottom Layer w10: v1(1835.44,699.21) 1990,854 1990,948 2025,983 v1(2049,983)
NetJ2_1: J2.1 R1.1 | length 755.2
  Top Layer w20: v2(839,1068) R1.1
  Top Layer w30: v2(1218,1206) 1346,1206 1371,1231 J2.1
  Bottom Layer w30: v2(839,1068) 889,1118 977,1118 1065,1206 v2(1218,1206)
NetJ3_2: J3.2 Q1.2 R8.2 | length 258.4
  Top Layer w10: Q1.2 Q1.2@1595,1352.65
  Top Layer w20: J3.2 1531,1456 R8.2 Q1.2@1595,1352.65
NetJ6_2: J6.2 U3.2 | length 209.4
  Top Layer w20: U3.2 1271,1015 1293,1037 1354,1037 1374,1057 J6.2
NetJ9_1: J9.1 TP3.1 U4.5 | length 492.1
  Top Layer w10: U4.5@386.72,1000.96 386.72,964.28 474,877 J9.1 TP3.1@580,651
NetR19_1: R19.1 U3.13 | length 175.8
  Top Layer w10: R19.1 R19.1@1271,588
  Top Layer w20: R19.1 U3.13@1270,761.4
OFF#: J7.2 R18.1 U4.6 | length 666.8
  Top Layer w6: U4.6 v1@507.89,1016.11
  Top Layer w10: J7.2 R18.1 v1(440.77,715)
  Bottom Layer w10: v1(440.77,715) 508,782.23 v1(508,1016)
ON#: J5.2 R17.1 U4.7 | length 577.7
  Top Layer w6: U4.7 439.22,1029.89
  Top Layer w10: J5.2 247.5,1312.89 R17.1 409.56,1312.89 475,1247.45 475,1066.89 439.22,1031.11
VREF1V65: C11.2 R6.1 R12.2 U3.6 | length 409.6
  Top Layer w10: R6.1@900,739 901,740 R6.1@902,741 ; R12.2 R12.2@911.18,853.18
  Top Layer w20: C11.2 1058.69,928.69 1071,941 U3.6
  Top Layer w30: R6.1 901,740 901,843 R12.2 ; R12.2@911.18,853.18 C11.2
VREF4V3: C9.2 R4.1 R10.2 U3.4 U3.8 U3.10 | length 856.3
  Top Layer w10: 1151.5,1058 1152,1057.5
  Top Layer w20: U3.8 1021,803 1042,824 1099.63,824 ; R10.2 1067,1104 1113,1058 C9.2 ; U3.10 1121,802.63 1099.63,824 ; C9.2@1171,1054.57 U3.4 1171,895.37 1099.63,824
  Top Layer w50: R10.2 R4.1
VREFCLK: C15.1 D8.2 R23.2 U4.1 | length 331.2
  Top Layer w6: R23.2 269.67,1043.67 U4.1
  Top Layer w20: D8.2 264.31,1031.69 R23.2 261,1082.56 293.45,1115 C15.1
VUVLO: R1.2 R3.2 U3.5 | length 284.7
  Top Layer w10: R3.2@1000.71,1175.71 R3.2 ; 1120.26,1008.74 1121,1008.74
  Top Layer w20: R1.2 1032.71,1036 1093,1036 1120.26,1008.74 ; U3.5 1121,1008.74
  Top Layer w50: R1.2 R3.2@1000.71,1175.71
pads on no net: FID1.1 FID2.1 FID3.1 H1.1 H2.1 H3.1 H4.1 SH-J1.0 SH-J2.0 SH-J3.0 SH-J4.0 SH-J6.0 SH-J7.0 SH-J8.0 U4.3

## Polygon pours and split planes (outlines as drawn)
GND on Bottom Layer "BOTTOM_LAYER_GND_P006" (solid, remove dead copper, pour order 6): 20,20 2680,20 2680,1980 20,1980
GND on Top Layer "TOP_LAYER_GND_P002" (solid, remove dead copper, pour order 2): 20,20 2680,20 2680,1980 20,1980

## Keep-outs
Keep-Out Layer:
  text ".Layer_Name" at 577,-858.49 h60

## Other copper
Top Layer:
  region net HV1: 2180.25,983.75 2133.25,983.75 2100.75,1002.75 2100.75,1048.75 2100.75,1207.75 2143,1250 2143,1384.75 2173.5,1415.25 2274.25,1415.25 2490.75,1415.25 2555.75,1366.75 2555.75,1180.67 2555.75,1048.75 2490.75,983.75 2331.25,983.75
  region net HV2: 2180.5,540.25 2101,605.25 2101,959.82 2132.33,971.75 2491,971.75 2556,915.75 2556,764.75 2556,605.25 2491,540.25 2272,540.25
  region net GND: 2030,1412.94 2030,1487 1932,1487 1932,1422.94 1907,1422.94 1855.5,1422.94 1850.25,1417.69 1845.5,1412.94 1845.5,1356.94 1855.5,1356.94 1979.16,1356.94 1992.21,1370 1992.21,1412.94
  region net GND: 885,1355 871,1341 871,1248 1021,1248 1021,1341 1007,1355
  region net GND: 848,1151 862,1142 955,1142 955,1217 862,1217 848,1203
  region net GND: 724,819 738,810 854,810 854,847 854,885 738,885 724,871
  region net GND: 308.7,1256.69 294.7,1242.69 294.7,1149.69 444.7,1149.69 444.7,1242.69 430.7,1256.69
  text ".Layer_Name" at 577,-858.49 h60
Bottom Layer:
  text ".Layer_Name" at 577,-858.49 h60

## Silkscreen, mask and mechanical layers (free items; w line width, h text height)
Top Overlay:
  text "ON" at -638,2785 h50 r90
  text "ISBA-EVM-01064 Rev A" at 999,1817 h70
  text "3V3" at 49,1363 h72.83
  text "ON" at 71,1263 h72.83
  text "AC1" at 2374,1220 h72.83
  text "GND" at 31,1160 h72.83
  text "ON" at 644,1056 h72.83
  text "3V3" at 44,796 h72.83
  text "AC2" at 2379,699 h72.83
  text "OFF" at 39,693 h72.83
  text "GND" at 28,593 h72.83
  text "GND" at 2193,426 h72.83
  text "GND" at 726.38,423 h72.83
  text "GND" at 1458,423 h72.83
  text ".Layer_Name" at 577,-858.49 h60
Bottom Overlay:
  text ".Layer_Name" at 577,-858.49 h60
Top Paste:
  text ".Layer_Name" at 577,-858.49 h60
Bottom Paste:
  text ".Layer_Name" at 577,-858.49 h60
Top Solder:
  text ".Layer_Name" at 577,-858.49 h60
  text ".Layer_Name" at 577,-858.49 h60
Bottom Solder:
  text ".Layer_Name" at 577,-858.49 h60
Drill Guide:
  text ".Layer_Name" at 577,-858.49 h60
M1 Board Outline:
  lines w0: 0,2000 2700,2000
  lines w10: 0,0 0,2000 2700,2000 2700,0 0,0
  text ".Layer_Name" at 577,-858.49 h60
M2 Board Dimensions:
  rectangle: 0,-275 125,-150
  rectangle: 125,-400 500,-275
  lines w7: 0,-275 1000,-275 ; 125,-400 125,-150 ; 250,-400 250,-150 ; 500,-400 500,-150 ; 750,-400 750,-150 ; 0,-400 1000,-400 1000,-150 0,-150 0,-400
  text ".Layer_Name" at 577,-858.49 h60
M3 3D STEP Top:
  text ".Layer_Name" at 577,-858.49 h60
M4 3D STEP Bottom:
  text ".Layer_Name" at 577,-858.49 h60
M5 Assembly Top:
  lines w10: -292,-930.17 6308,-930.17 ; -292,-726.83 6310,-726.83 ; -292,-523.5 -292,-1133.5 3713,-1133.5 6310,-1133.5 6310,-523.5 -291.5,-523.5 -291.5,-1133.5 1284,-1133.5 ; 2173,-1133.5 2173,-523.5 ; 3440,-726.83 3440,-523.5 ; 4280,-726.83 4280,-523.5 ; 4902,-1140 4902,-937.17
  text "COMPONENTS MARKED 'DNP' SHOULD NOT BE POPULATED." at 1153.5,-318.5 h60
  text "ASSEMBLY VARIANT:" at 1153,-434 h60
  text ".VariantName" at 2189,-434 h60
  text "PCB VIEWED FROM TOP SIDE" at -228.5,-655.67 h60
  text "BOARD #:" at 2248,-655.67 h60
  text ".PRJ_Number" at 2793.5,-655.67 h60
  text "REV:" at 3638,-655.67 h60
  text ".PCB_Rev" at 3929.5,-655.67 h60
  text "SVN REV:" at 4476,-655.67 h60
  text ".VersionControl_RevNumber" at 4982,-655.67 h60
  text "TID #:" at 2248,-859 h60
  text ".TID" at 2793.5,-859 h60
  text "PLOT NAME =" at -228.5,-1064.34 h60
  text ".plot_File_Name" at 577,-1064.34 h60
  text "GENERATED    :" at 2250,-1064.34 h60
  text ".Print_Date" at 3119.5,-1064.34 h60
  text ".Print_Time" at 3848.5,-1064.34 h60
  text "TEXAS INSTRUMENTS" at 5113,-1064.34 h60
M6 Assembly Bottom:
  lines w10: -292.5,-727.33 6309.5,-727.33 ; -290.5,-930.67 6309.5,-930.67 ; 1115.5,-1140.5 1115.5,-937.67 ; 1737.5,-727.33 1737.5,-524 ; 2577.5,-727.33 2577.5,-524 ; 3844.5,-1134 3844.5,-524 ; 4733.5,-1134 6309,-1134 6309,-524 -292.5,-524 -292.5,-1134 2304.5,-1134 6309.5,-1134 6309.5,-524
  text "COMPONENTS MARKED 'DNP' SHOULD NOT BE POPULATED." at 6102,-318 h60
  text ".VariantName" at 5058,-434 h60
  text "ASSEMBLY VARIANT:" at 6097,-434 h60
  text ".VersionControl_RevNumber" at 1035.5,-656.17 h60
  text "SVN REV:" at 1541.5,-656.17 h60
  text ".PCB_Rev" at 2088,-656.17 h60
  text "REV:" at 2379.5,-656.17 h60
  text ".PRJ_Number" at 3224,-656.17 h60
  text "BOARD #:" at 3769.5,-656.17 h60
  text "PCB VIEWED FROM BOTTOM SIDE" at 6246,-656.17 h60
  text ".TID" at 3224,-859.5 h60
  text "TID #:" at 3769.5,-859.5 h60
  text "TEXAS INSTRUMENTS" at 904.5,-1064.84 h60
  text ".Print_Time" at 2169,-1064.84 h60
  text ".Print_Date" at 2898,-1064.84 h60
  text "GENERATED    :" at 3767.5,-1064.84 h60
  text ".plot_File_Name" at 5440.5,-1064.84 h60
  text "PLOT NAME =" at 6246,-1064.84 h60
M9 Title Sheet:
  drawing of 57 lines, arcs and shapes, not listed
  text "1" at 739.84,8036.5 h70
  text "2" at 3235.5,8036.5 h70
  text "3" at 5724.84,8036.5 h70
  text "4" at 8231.51,8036.5 h70
  text "5" at 10730.5,8036.5 h70
  text "6" at 13235.5,8036.5 h70
  text "A" at -416.5,6893.5 h70
  text "A" at 14383.5,6893.5 h70
  text "B" at -416.5,4513.5 h70
  text "B" at 14383.5,4513.5 h70
  text "C" at -416.5,2138.5 h70
  text "C" at 14383.5,2138.5 h70
  text "PROJECT TITLE:" at 11343.5,277.5 h45
  text ".PRJ_Title" at 11393.5,144.17 h70
  text "DESIGNED FOR:" at 11343.5,-23.5 h45
  text ".PRJ_Customer" at 11393.5,-163.5 h70
  text "D" at -416.5,-231.5 h70
  text "D" at 14383.5,-231.5 h70
  text "FILE NAME:" at 11343.5,-323.5 h45
  text ".PCB_File_Name_No_Path" at 11393.5,-443.5 h70
  text "Texas Instruments (TI) and/or its licensors do not warrant the accuracy or completeness of this specification" at 6374,-605.34 h45
  text "ENGINEER:" at 11343.5,-613.5 h45
  text "LAYOUT BY:" at 12848.5,-613.5 h45
  text "or any information contained therein. TI and/or its licensors do not warrant that this design will meet" at 6329.01,-718 h45
  text ".PRJ_Engineer" at 11393.5,-768.49 h70
  text ".PCB_Layout" at 12899,-768.49 h70
  text "the specifications, will be suitable for your application or fit for any particular purpose, or will operate in" at 6329.01,-830.67 h45
  text ".Layer_Name" at 577,-858.49 h60
  text "ALTIUM DESIGNER VERSION:" at 12848.5,-923.5 h45
  text "an implementation. TI and/or its licensors do not warrant that the design is production worthy. You should" at 6329.01,-943.33 h45
  text "completely validate and test your design implementation to confirm the system functionality for your application." at 6374,-1056 h45
  text ".print_Scale" at 11393.5,-1056.83 h70
  text ".Application_BuildNumber" at 12899,-1056.83 h70
  text "1" at 739.84,-1263.5 h70
  text "2" at 3235.5,-1263.5 h70
  text "3" at 5724.84,-1263.5 h70
  text "4" at 8231.51,-1263.5 h70
  text "5" at 10730.5,-1263.5 h70
  text "6" at 13235.5,-1263.5 h70
M10 Fab Notes:
  drawing of 173 lines, arcs and shapes, not listed
  text "DESIGN INFORMATION" at 12378.02,6201 h60
  text "MIN. TRACK WIDTH:" at 11733.46,6021 h60
  text "8" at 12829.7,6021 h60
  text "MIL" at 12984.46,6021 h60
  text "MIN. CLEARANCE:" at 11733.46,5889 h60
  text "0.2" at 12769.7,5889 h60
  text "mm" at 12984.46,5889 h60
  text "MIN. VIA PAD SIZE:" at 11733.46,5757 h60
  text "24" at 12799.71,5757 h60
  text "MIL" at 12984.46,5757 h60
  text "0.05mm (2MIL)" at 12428.46,5615.29 h60
  text "MINIMUM ANNULAR RING" at 11404.23,5611 h60
  text "EXTERNAL" at 13136.46,5611 h60
  text "PER" at 11604.23,5493 h60
  text "IPC-D-275 CLASS 2 LEVEL C" at 11824.23,5493 h60
  text "MIL, HOLES" at 13312.46,5380.71 h60
  text "+/-" at 12920,5380 h60
  text "+/-" at 13774,5380 h60
  text "REGISTRATION TOLERANCES:" at 11404.23,5375 h60
  text "METAL" at 12604,5375 h60
  text "5" at 13180.2,5375 h60
  text "3" at 14013.2,5375 h60
  text "MIL" at 14129.46,5375 h60
  text "+/-" at 13774,5262 h60
  text "HOLE SIZE TOLERANCE (UNLESS OTHERWISE SPECIFIED):" at 11404.23,5257 h60
  text "3" at 14013.2,5257 h60
  text "MIL" at 14129.46,5257 h60
  text "MATERIAL:" at 11329.46,5047.54 h60
  text "FR-4 High Tg" at 12315.9,4907.21 h60
  text "FR-408" at 11750.46,4898.64 h60
  text "OTHER" at 13238.46,4898.64 h60
  text "X" at 12161,4895 h60
  text "62 MIL (1.6mm) +/-10%" at 12070.56,4735.92 h60
  text "THICKNESS:" at 11404.23,4731.64 h60
  text "X" at 11942.4,4731.64 h60
  text "OTHER" at 13355.46,4731.64 h60
  text "TOLERANCE:" at 11404.23,4573.64 h60
  text "X" at 12243.53,4573.64 h60
  text "ANSI IPC-6012 TYPE 3 CLASS 2" at 12430.48,4573.64 h60
  text "OTHER +/-" at 12430.46,4417.64 h60
  text "BOW & TWIST:" at 11404.23,4260.64 h60
  text "X" at 12243.53,4260.64 h60
  text "ANSI IPC-6012 TYPE 3 CLASS 2" at 12430.48,4260.64 h60
  text "OTHER +/-" at 12430.46,4102.13 h60
  text "DRILLING:" at 11329.46,3963.64 h60
  text "REFERENCE:" at 11404.23,3846.64 h60
  text "X" at 12052.46,3846.64 h60
  text "AS SHOWN" at 12239.46,3846.64 h60
  text "X" at 12953.46,3846.64 h60
  text "NC_DRILL FILES" at 13090.46,3846.64 h60
  text "PTH COPPER THICKNESS:" at 11404.23,3688.64 h60
  text "X" at 12534.46,3688.64 h60
  text "20-30 um" at 12671.46,3688.64 h60
  text "OTHER" at 13388.46,3688.64 h60
  text "BOARD FINISH:" at 11329.46,3529.64 h60
  text "SILKSCREEN:" at 11484.68,3411.64 h60
  text "X" at 12433.46,3411.64 h60
  text "TOP" at 12559.46,3411.64 h60
  text "BOTTOM" at 13070.46,3411.64 h60
  text "SILKSCREEN COLOR:" at 11484.68,3244.64 h60
  text "X" at 12432.42,3244.64 h60
  text "WHITE" at 12559.46,3244.64 h60
  text "OTHER" at 13070.46,3244.64 h60
  text "X" at 12563.42,3085.44 h60
  text "GREEN" at 12690.46,3085.44 h60
  text "OTHER" at 13308.46,3085.44 h60
  text "SOLDER RESIST COLOR:" at 11484.68,3074.64 h60
  text "X" at 12563.42,2915.44 h60
  text "MATTE" at 12690.46,2915.44 h60
  text "SEMI-GLOSS" at 13308,2914.8 h60
  text "IMMERSION GOLD (ENIG)" at 12390.46,2726.92 h60
  text "ENEPIG" at 13728,2723.64 h60
  text "SURFACE FINISH:" at 11329.46,2722.64 h60
  text "X" at 12203.51,2722.64 h60
  text "IMM. TIN/SILVER OR EQUIV" at 11659,2565.64 h60
  text "OTHER" at 13090.46,2565.64 h60
  text "ARRAY/PANEL:" at 11329.46,2386.64 h60
  text "CUT AND TRIM PER M1 BOARD OUTLINE" at 12390.46,2382.35 h60
  text "N.C. ROUTE" at 12390.46,2230.64 h60
  text "X" at 13069.46,2230.64 h60
  text "V. SCORE" at 13256.46,2230.64 h60
  text "CERTIFICATION:" at 11329.46,2093.64 h60
  text "MATERIALS AND WORKMANSHIP FOR ALL PCBS" at 12054.46,2093.64 h60
  text "TO MEET OR EXCEED THE REQUIREMENTS OF:" at 12054.46,1995.64 h60
  text "X" at 11680.96,1859.13 h60
  text "ANSI IPC-A-600F CLASS ->" at 11819.96,1859.13 h60
  text "X" at 13459.02,1859.13 h60
  text "2" at 13577.96,1859.14 h60
  text "1" at 13262.96,1857.64 h60
  text "3" at 13931.96,1857.64 h60
  text "X" at 12495.02,1699.64 h60
  text "RoHS" at 12631.96,1699.64 h60
  text "OTHER" at 13276.36,1699.64 h60
  text "PER ORDER" at 13673.42,1699.64 h60
  text "ALL BOARDS MUST MEET OR EXCEED UL94-V0 REQUIREMENTS." at 11357,1534 h60
  text "PCB MUST BEAR THE UL94V-0 UL REGISTERED MATERIAL ID NUMBER" at 11357,1414 h60
  text "ADDITIONAL REQUIREMENTS:" at 11329.46,1240.64 h60
  text "MICROSECTION:" at 11404.23,1125.64 h60
  text "YES" at 12309.96,1125.64 h60
  text "REQUIRED" at 13171.46,969.49 h60
  text "BARE BOARD ELEC. TEST:" at 11404.23,966.64 h60
  text "NONE" at 12709.96,966.64 h60
  text "X" at 13044.46,966.64 h60
  text "PER ORDER" at 13763.46,966.64 h60
  text ".Layer_Name" at 577,-858.49 h60
M11 Gerber Information:
  lines w10: -292,-930.17 6308,-930.17 ; -292,-726.83 6310,-726.83 ; -292,-523.5 -292,-1133.5 3713,-1133.5 6310,-1133.5 6310,-523.5 -291.5,-523.5 -291.5,-1133.5 1284,-1133.5 ; 2173,-1133.5 2173,-523.5 ; 3440,-726.83 3440,-523.5 ; 4280,-726.83 4280,-523.5 ; 4902,-1140 4902,-937.17
  text "ALL ARTWORK VIEWED FROM TOP SIDE" at -228.5,-655.67 h60
  text "BOARD #:" at 2248,-655.67 h60
  text ".PRJ_Number" at 2793.5,-655.67 h60
  text "REV:" at 3638,-655.67 h60
  text ".PCB_Rev" at 3929.5,-655.67 h60
  text "SVN REV:" at 4476,-655.67 h60
  text ".VersionControl_RevNumber" at 4982,-655.67 h60
  text "LAYER NAME =" at -228.5,-858.49 h60
  text "TID #:" at 2248,-859 h60
  text ".TID" at 2793.5,-859 h60
  text "PLOT NAME =" at -228.5,-1064.34 h60
  text ".plot_File_Name" at 577,-1064.34 h60
  text "GENERATED    :" at 2250,-1064.34 h60
  text ".Print_Date" at 3119.5,-1064.34 h60
  text ".Print_Time" at 3848.5,-1064.34 h60
  text "TEXAS INSTRUMENTS" at 5113,-1064.34 h60
M12 Stackup:
  drawing of 191 lines, arcs and shapes, not listed
  text "Layer" at 9790.34,7830 h60
  text "Name" at 10200.26,7830 h60
  text "Material" at 11130,7830 h60
  text "Thickness" at 11989.77,7830 h60
  text "Constant" at 12639.6,7830 h60
  text "Board Layer Stack" at 13209.46,7830 h60
  text "1" at 9790.34,7710 h60
  text "Top Overlay" at 10200.26,7710 h60
  text "2" at 9790.34,7590 h60
  text "Top Solder" at 10200.26,7590 h60
  text "Solder Resist" at 11130,7590 h60
  text "0.40mil" at 11989.77,7590 h60
  text "3.5" at 12639.6,7590 h60
  text "3" at 9790.34,7470 h60
  text "Top Layer" at 10200.26,7470 h60
  text "Copper" at 11130,7470 h60
  text "1.40mil" at 11989.77,7470 h60
  text "4" at 9790.34,7350 h60
  text "Dielectric1" at 10200.26,7350 h60
  text "FR-4" at 11130,7350 h60
  text "59.20mil" at 11989.77,7350 h60
  text "4.8" at 12639.6,7350 h60
  text "5" at 9790.34,7230 h60
  text "Bottom Layer" at 10200.26,7230 h60
  text "Copper" at 11130,7230 h60
  text "1.40mil" at 11989.77,7230 h60
  text "6" at 9790.34,7110 h60
  text "Bottom Solder" at 10200.26,7110 h60
  text "Solder Resist" at 11130,7110 h60
  text "0.40mil" at 11989.77,7110 h60
  text "3.5" at 12639.6,7110 h60
  text "7" at 9790.34,6990 h60
  text "Bottom Overlay" at 10200.26,6990 h60
  text ".Layer_Name" at 577,-858.49 h60
M13 Component Bodies Top:
  text ".Layer_Name" at 577,-858.49 h60
M14 Component Bodies Bottom:
  text ".Layer_Name" at 577,-858.49 h60
M15 Courtyards Top:
  text ".Layer_Name" at 577,-858.49 h60
M16 Courtyards Bottom:
  text ".Layer_Name" at 577,-858.49 h60
Drill Drawing:
  circle w10: c5348.9,2904.29 r22.14
  lines w10: 5326.76,2992.84 5337.83,2992.84 5348.9,2981.77 5359.97,2992.84 5371.04,2992.84 5359.97,3003.91 5371.04,3014.98 5359.97,3014.98 5348.9,3026.05 5337.83,3014.98 5326.76,3014.98 5337.83,3003.91 5326.76,2992.84 ; 5326.76,3081.4 5371.04,3081.4 5371.04,3125.67 5326.76,3125.67 5326.76,3081.4 ; 5326.76,3181.02 5348.9,3192.09 5371.04,3181.02 5359.97,3203.16 5371.04,3225.3 5348.9,3214.23 5326.76,3225.3 5337.83,3203.16 5326.76,3181.02 ; 5326.76,3291.71 5337.83,3291.71 5337.83,3280.64 5359.97,3280.64 5359.97,3291.71 5371.04,3291.71 5371.04,3313.85 5359.97,3313.85 5359.97,3324.92 5337.83,3324.92 5337.83,3313.85 5326.76,3313.85 5326.76,3291.71
  lines w12: 5286,2852.27 8398.94,2852.27 ; 5286,3350.38 8398.94,3350.38 ; 5601.63,2752.64 5601.63,3450 ; 5918.82,2752.64 5918.82,3450 ; 6540.56,2752.64 6540.56,3450 ; 6784.88,2752.64 6784.88,3450 ; 7145.22,2752.64 7145.22,3450 ; 7854.73,2752.64 7854.73,3450 ; 5286,2752.64 8398.94,2752.64 8398.94,3450 5286,3450 5286,2752.64
  text "Symbol" at 5345.77,3380.26 h72
  text "Quantity" at 5631.52,3380.26 h72
  text "Finished Hole Size" at 5948.7,3380.26 h72
  text "Plated" at 6570.45,3380.26 h72
  text "Hole Type" at 6814.77,3380.26 h72
  text "Drill Layer Pair" at 7175.11,3380.26 h72
  text "Hole Tolerance" at 7884.62,3380.26 h72
  text "163" at 5631.52,3280.64 h60
  text "10.00mil (0.254mm)" at 5948.7,3280.64 h60
  text "PTH" at 6570.45,3280.64 h60
  text "Round" at 6814.77,3280.64 h60
  text "Top Layer - Bottom Layer" at 7175.11,3280.64 h60
  text "2" at 5631.52,3181.02 h60
  text "16.00mil (0.406mm)" at 5948.7,3181.02 h60
  text "PTH" at 6570.45,3181.02 h60
  text "Round" at 6814.77,3181.02 h60
  text "Top Layer - Bottom Layer" at 7175.11,3181.02 h60
  text "19" at 5631.52,3081.4 h60
  text "39.37mil (1.000mm)" at 5948.7,3081.4 h60
  text "PTH" at 6570.45,3081.4 h60
  text "Round" at 6814.77,3081.4 h60
  text "Top Layer - Bottom Layer" at 7175.11,3081.4 h60
  text "4" at 5631.52,2981.77 h60
  text "43.31mil (1.100mm)" at 5948.7,2981.77 h60
  text "PTH" at 6570.45,2981.77 h60
  text "Round" at 6814.77,2981.77 h60
  text "Top Layer - Bottom Layer" at 7175.11,2981.77 h60
  text "4" at 5631.52,2882.15 h60
  text "125.98mil (3.200mm)" at 5948.7,2882.15 h60
  text "PTH" at 6570.45,2882.15 h60
  text "Round" at 6814.77,2882.15 h60
  text "Top Layer - Bottom Layer" at 7175.11,2882.15 h60
  text "192 Total" at 5631.52,2782.53 h60
  text ".Layer_Name" at 577,-858.49 h60
M17 Embedded Cavity:
  text ".Layer_Name" at 577,-858.49 h60
M18 Embedded Assembly:
  text ".Layer_Name" at 577,-858.49 h60
M19 Embedded Keepout:
  text ".Layer_Name" at 577,-858.49 h60

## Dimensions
0,-400 to 1000,-400 on M2 Board Dimensions
0,0 to 0,2000 on M2 Board Dimensions
0,0 to 2700,0 on M2 Board Dimensions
